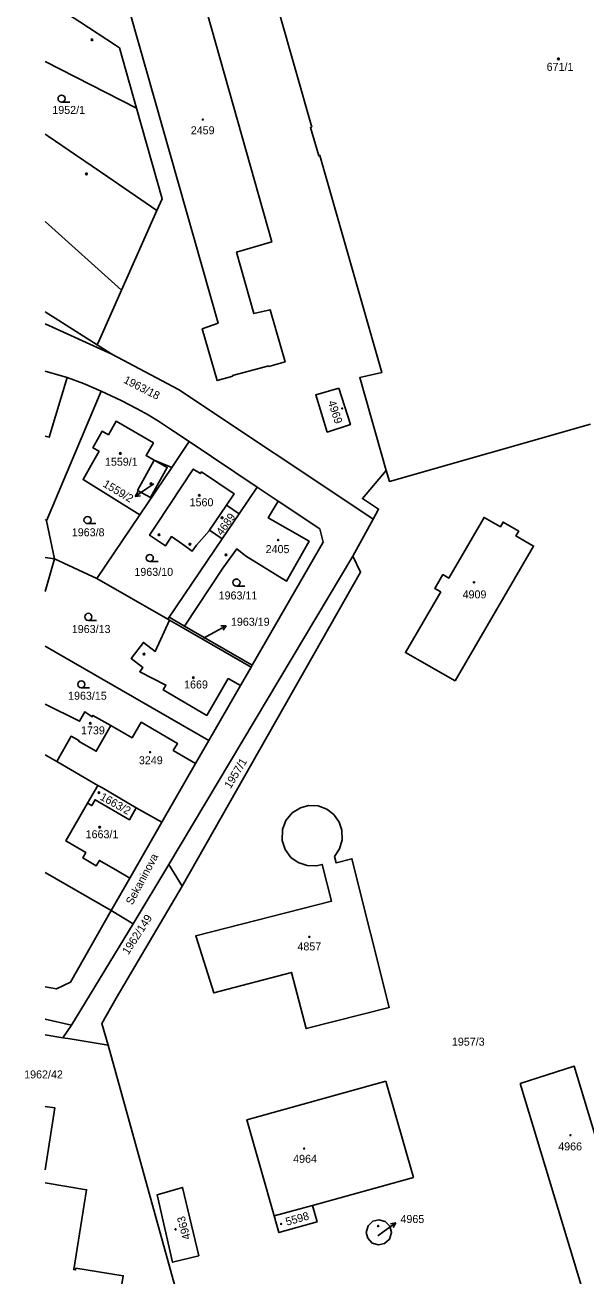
# Model space of a CAD drawing. Extents: x -667048 to -665920, y -1108425 to -1107247.
# Drawn here: x -667047.7 to -666928.5, y -1107866.2 to -1107600.6 of the extents above; entities that cross this region are included whole.
import ezdxf

# ---------------------------------------------------------------- set-up
doc = ezdxf.new("R2010")
doc.units = 0
for name, color, linetype in [('Default', 7, 'Continuous'), ('Hranice parcel', 7, 'Continuous'), ('Parcelní čísla', 7, 'Continuous'), ('Pop_ PČ_ popisy', 7, 'Continuous'), ('Značky budov', 7, 'Continuous'), ('Značky kultur', 7, 'Continuous')]:
    doc.layers.add(name, color=color, linetype=linetype)

# ---------------------------------------------------------------- blocks, each defined once
blk = doc.blocks.new('3.041')
at = {"layer": 'Default'}
blk.add_line((8, 0), (1758, 0), dxfattribs=at)
blk.add_circle((8, 750), 750, dxfattribs=at)
blk = doc.blocks.new('4.021')
at = {"layer": 'Default'}
blk.add_circle((-7, 1), 175, dxfattribs=at)
blk = doc.blocks.new('10291')
at = {"layer": 'Default'}
for p, q in [((0, 3001), (-500, 2001)), ((0, 1), (0, 3001)), ((0, 3001), (500, 2001))]:
    blk.add_line(p, q, dxfattribs=at)

msp = doc.modelspace()

# ---------------------------------------------------------------- linework, layer by layer
at = {"layer": 'Hranice parcel'}
for points in [[(-666970.95, -1107695.22), (-666976.59, -1107675.49), (-666971.89, -1107674.42), (-666985.05, -1107628.31), (-666985.31, -1107628.39), (-666987.06, -1107622.39), (-666986.8, -1107622.31), (-667000.62, -1107573.5), (-667000.76, -1107573.54), (-667001.78, -1107570.07), (-666998.23, -1107568.96), (-666998.83, -1107566.87), (-666996.16, -1107566.11), (-666996.94, -1107562.47), (-666921.16, -1107540.78), (-666917.42, -1107543.09), (-666913.29, -1107542), (-666908.38, -1107559.19), (-666898.23, -1107556.28), (-666897.4, -1107559.14)], [(-667021.52, -1107584.2), (-667013.51, -1107581.95), (-666995.3, -1107646.66), (-667002.77, -1107648.84), (-666999.12, -1107661.88), (-666995.66, -1107661.07), (-666992.44, -1107672.12), (-666995.9, -1107673.13), (-666995.94, -1107672.98)], [(-666995.94, -1107672.98), (-667003.61, -1107675.01), (-667003.57, -1107675.15), (-667006.92, -1107676.1), (-667010.04, -1107665.09), (-667006.69, -1107663.93), (-667028.7, -1107586.32)], [(-667043.07, -1107595.39), (-667036.05, -1107599.95), (-667028.46, -1107604.89), (-667027.63, -1107605.43)], [(-667027.63, -1107605.43), (-667024.02, -1107618.24)], [(-667024.02, -1107618.24), (-667043.46, -1107608.33)], [(-667024.02, -1107618.24), (-667018.59, -1107637.51), (-667019.68, -1107639.97)], [(-667043.46, -1107623.77), (-667042.77, -1107624.24), (-667036.78, -1107628.32), (-667030.12, -1107632.86)], [(-667030.12, -1107632.86), (-667019.68, -1107639.97)], [(-667027.19, -1107656.94), (-667043.46, -1107642.32)], [(-667019.68, -1107639.97), (-667027.19, -1107656.94)], [(-667027.19, -1107656.94), (-667031.86, -1107667.48), (-667032.38, -1107668.52)], [(-667043.46, -1107661.48), (-667032.38, -1107668.52)], [(-667029.24, -1107670.52), (-667043.46, -1107664.08)], [(-667032.38, -1107668.52), (-667029.24, -1107670.52)], [(-667029.24, -1107670.52), (-667015.09, -1107677.99), (-666974.26, -1107705.21)], [(-667043.46, -1107674.12), (-667038.79, -1107675.48)], [(-667043.46, -1107687.89), (-667042.57, -1107688.14), (-667038.79, -1107675.48)], [(-667038.79, -1107675.48), (-667035.28, -1107676.72), (-667031.56, -1107678.37)], [(-667043.12, -1107705.86), (-667031.56, -1107678.37)], [(-667031.56, -1107678.37), (-667027.28, -1107680.37), (-667023.88, -1107682.12), (-667021.55, -1107683.4), (-667019.34, -1107684.73), (-667016.79, -1107686.46), (-667012.8, -1107689.05)], [(-666981.07, -1107677.7), (-666978.58, -1107685.45), (-666983.5, -1107687.03), (-666985.93, -1107679.17), (-666981.07, -1107677.7)], [(-667016.53, -1107694.56), (-667020.24, -1107693.01), (-667021.99, -1107692.03), (-667020.44, -1107689.3), (-667028.37, -1107684.75), (-667030, -1107687.62), (-667031.32, -1107686.88), (-667031.94, -1107687.98), (-667033.3, -1107690.39), (-667031.99, -1107691.13), (-667033.67, -1107694.09), (-667035.39, -1107697.13), (-667023.34, -1107704.62)], [(-666927.58, -1107685.38), (-666970.29, -1107697.51), (-666970.95, -1107695.22)], [(-667016.53, -1107694.56), (-667012.8, -1107689.05)], [(-667012.8, -1107689.05), (-666998.38, -1107698.74)], [(-667020.24, -1107693.01), (-667017.5, -1107694.54), (-667021.06, -1107700.95), (-667023.81, -1107699.42), (-667020.24, -1107693.01)], [(-667023.34, -1107704.62), (-667016.53, -1107694.56)], [(-667004.92, -1107702.55), (-667003.3, -1107700.14), (-667010.21, -1107695.52), (-667010.44, -1107695.86), (-667011.95, -1107694.9), (-667016.94, -1107702.44), (-667019.97, -1107707.01), (-667021.25, -1107708.95), (-667017.86, -1107711.18), (-667016.6, -1107709.22), (-667014.22, -1107710.84), (-667012.17, -1107712.33), (-667011.26, -1107711.06), (-667008.6, -1107708.03), (-667008.49, -1107707.87)], [(-666973.75, -1107705.53), (-666972.58, -1107703.4), (-666976.03, -1107701.17), (-666970.95, -1107695.22)], [(-667002.2, -1107704.37), (-666998.38, -1107698.74)], [(-666998.38, -1107698.74), (-666993.92, -1107701.7)], [(-666993.92, -1107701.7), (-666996.03, -1107705.26), (-666987.35, -1107710.2), (-666992.13, -1107718.67), (-667000.87, -1107713.31), (-667002.68, -1107711.81), (-667005.65, -1107715.91), (-667013.81, -1107728.26)], [(-667008.49, -1107707.87), (-667004.92, -1107702.55)], [(-667002.2, -1107704.37), (-667004.92, -1107702.55)], [(-666985.05, -1107707.59), (-666993.92, -1107701.7)], [(-667043.12, -1107705.86), (-667043.46, -1107705.61)], [(-667041.46, -1107713.99), (-667043.12, -1107705.86)], [(-667032.48, -1107718.11), (-667023.34, -1107704.62)], [(-667005.79, -1107709.69), (-667002.2, -1107704.37)], [(-666973.75, -1107705.53), (-666978.06, -1107713.42)], [(-666974.26, -1107705.21), (-666973.75, -1107705.53)], [(-666959.36, -1107720.99), (-666960.62, -1107720.26), (-666958.91, -1107717.31), (-666957.66, -1107718.04), (-666950.19, -1107705.15), (-666946.72, -1107707.16), (-666946.14, -1107706.16), (-666942.82, -1107708.09), (-666943.4, -1107709.08), (-666939.65, -1107711.25), (-666956.32, -1107739.85)], [(-667008.49, -1107707.87), (-667005.79, -1107709.69)], [(-666999.44, -1107736.57), (-666984.38, -1107710.4), (-666985.05, -1107707.59)], [(-667017.09, -1107726.36), (-667005.79, -1107709.69)], [(-667041.46, -1107713.99), (-667043.46, -1107713.67)], [(-667043.46, -1107720.92), (-667041.46, -1107713.99)], [(-667041.46, -1107713.99), (-667032.48, -1107718.11)], [(-666978.06, -1107713.42), (-667017.13, -1107778.9)], [(-667014.34, -1107783.5), (-666976.43, -1107716.82), (-666978.06, -1107713.42)], [(-667032.48, -1107718.11), (-667017.35, -1107726.75)], [(-666956.32, -1107739.85), (-666966.89, -1107733.85), (-666959.36, -1107720.99)], [(-667016.98, -1107726.96), (-667020.05, -1107733.63), (-667022.56, -1107731.7), (-667025.18, -1107735.1), (-667022.65, -1107737.04), (-667023.35, -1107737.94), (-667017.77, -1107740.76), (-667018.37, -1107741.8), (-667009.09, -1107747.2), (-667004.53, -1107739.38), (-667001.92, -1107740.86)], [(-667017.35, -1107726.75), (-667017.09, -1107726.36)], [(-667016.98, -1107726.96), (-667017.35, -1107726.75)], [(-667013.81, -1107728.26), (-667017.09, -1107726.36)], [(-666999.67, -1107736.98), (-667014.06, -1107728.65), (-667016.98, -1107726.96)], [(-667013.81, -1107728.26), (-666999.44, -1107736.57)], [(-667008.67, -1107752.53), (-667043.46, -1107732.53)], [(-666999.67, -1107736.98), (-667001.92, -1107740.86)], [(-666999.44, -1107736.57), (-666999.67, -1107736.98)], [(-667001.92, -1107740.86), (-667008.67, -1107752.53)], [(-667043.46, -1107744.79), (-667036.12, -1107748.44), (-667034.97, -1107746.43), (-667033.43, -1107747.48), (-667033.27, -1107747.2), (-667029.48, -1107749.37)], [(-667040.97, -1107756.99), (-667037.93, -1107751.64), (-667036.26, -1107752.51), (-667036.34, -1107752.66), (-667032.59, -1107754.81), (-667029.48, -1107749.37)], [(-667029.48, -1107749.37), (-667024.97, -1107751.96), (-667023, -1107748.65), (-667015.34, -1107753.17), (-667016.22, -1107754.65), (-667014.51, -1107755.66), (-667011.49, -1107757.44)], [(-667011.49, -1107757.44), (-667008.67, -1107752.53)], [(-667043.46, -1107755.56), (-667040.97, -1107756.99)], [(-667032.26, -1107762.07), (-667040.97, -1107756.99)], [(-667011.49, -1107757.44), (-667018.64, -1107769.87)], [(-667032.26, -1107762.07), (-667034.41, -1107765.82)], [(-667024.07, -1107766.86), (-667031.39, -1107762.52), (-667032.26, -1107762.07)], [(-667034.41, -1107765.82), (-667039.03, -1107773.87), (-667034.76, -1107776.34), (-667035.42, -1107777.47), (-667032.56, -1107779.14), (-667031.9, -1107778), (-667028.04, -1107780.24), (-667025.46, -1107781.74)], [(-667024.07, -1107766.86), (-667025.52, -1107769.36), (-667032.81, -1107765.11), (-667033.48, -1107766.34), (-667034.41, -1107765.82)], [(-667018.64, -1107769.87), (-667024.07, -1107766.86)], [(-666990.92, -1107767.86), (-666989.2, -1107766.82), (-666987.46, -1107766.36), (-666985.41, -1107766.44), (-666983.57, -1107767.14), (-666982.08, -1107768.26), (-666980.98, -1107769.85), (-666980.37, -1107771.57), (-666980.35, -1107773.6), (-666980.9, -1107775.51), (-666981.96, -1107777.15), (-666981.63, -1107778.49), (-666978.24, -1107777.63), (-666970.31, -1107809.21), (-666987.95, -1107813.7), (-666991.09, -1107801.78), (-667007.6, -1107806.13), (-667011.45, -1107793.99), (-666982.58, -1107786.64), (-666984.56, -1107778.86), (-666985.75, -1107779.16), (-666987.76, -1107779.11), (-666989.71, -1107778.46), (-666991.21, -1107777.38), (-666992.46, -1107775.7), (-666993.08, -1107773.79), (-666992.99, -1107771.46), (-666992.27, -1107769.53), (-666990.92, -1107767.86)], [(-667018.64, -1107769.87), (-667025.46, -1107781.74)], [(-667024.75, -1107791.46), (-667017.13, -1107778.9)], [(-667017.13, -1107778.9), (-667014.34, -1107783.5)], [(-667043.46, -1107780.58), (-667029.42, -1107788.65)], [(-667025.46, -1107781.74), (-667029.42, -1107788.65)], [(-667014.34, -1107783.5), (-667028.38, -1107807.25), (-667031.41, -1107812.61), (-667030.05, -1107817.21)], [(-667043.46, -1107804.86), (-667041.01, -1107805.24), (-667038.08, -1107803.86), (-667029.42, -1107788.65)], [(-667029.42, -1107788.65), (-667024.75, -1107791.46)], [(-667037.81, -1107812.96), (-667024.75, -1107791.46)], [(-667037.81, -1107812.96), (-667043.46, -1107811.71)], [(-667039.67, -1107815.65), (-667037.81, -1107812.96)], [(-667043.46, -1107815.03), (-667039.67, -1107815.65)], [(-667030.05, -1107817.21), (-667038.12, -1107815.9), (-667039.67, -1107815.65)], [(-667030.05, -1107817.21), (-667003.54, -1107912.79)], [(-666942.5, -1107825.4), (-666931.02, -1107821.66), (-666917.67, -1107865.87), (-666929.14, -1107869.61), (-666942.5, -1107825.4)], [(-666994.78, -1107853.5), (-667000.6, -1107833.05), (-666971.07, -1107824.87)], [(-666971.07, -1107824.87), (-666965.16, -1107845.35)], [(-667043.46, -1107830.23), (-667041.35, -1107830.57), (-667043.46, -1107843.7)], [(-667043.46, -1107846.47), (-667034.62, -1107847.92), (-667037.37, -1107864.87), (-667036.96, -1107864.94), (-667036.89, -1107864.56), (-667026.84, -1107866.2), (-667031.79, -1107896.83), (-667041.86, -1107895.2), (-667041.79, -1107894.82), (-667043.46, -1107894.55)], [(-666965.16, -1107845.35), (-666986.66, -1107851.25)], [(-667010.75, -1107861.94), (-667016.37, -1107863.34), (-667019.63, -1107849.01), (-667014.24, -1107847.43), (-667010.75, -1107861.94)], [(-666986.66, -1107851.25), (-666985.66, -1107854.76), (-666993.78, -1107857.01), (-666994.78, -1107853.5)], [(-666994.78, -1107853.5), (-666986.66, -1107851.25)], [(-666975.2, -1107856.98), (-666974.81, -1107855.58), (-666973.81, -1107854.63), (-666972.52, -1107854.3), (-666971.16, -1107854.67), (-666970.19, -1107855.65), (-666969.84, -1107856.98), (-666970.28, -1107858.45), (-666971.3, -1107859.36), (-666972.64, -1107859.65), (-666973.95, -1107859.24), (-666974.88, -1107858.24), (-666975.2, -1107856.98)]]:
    msp.add_lwpolyline(points, dxfattribs=at)
at = {"layer": 'Pop_ PČ_ popisy'}
for points in [[(-667020.33, -1107698.03), (-667021.82, -1107699.04)], [(-667009.82, -1107730.82), (-667007.59, -1107729.61)], [(-666972.78, -1107857.74), (-666971.38, -1107856.74)]]:
    msp.add_lwpolyline(points, dxfattribs=at)

# ---------------------------------------------------------------- block references
for p, xscale, yscale, rotation in [((-667021.82, -1107699.04), 0.001, 0.001, 124.00000003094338), ((-667007.59, -1107729.61), 0.001, 0.0010000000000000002, -61.00000001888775), ((-666971.38, -1107856.74), 0.0010000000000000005, 0.0010000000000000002, -53.99999995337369)]:
    msp.add_blockref('10291', p, dxfattribs=dict(at, xscale=xscale, yscale=yscale, rotation=rotation))
at = {"layer": 'Značky budov'}
for p, xscale, yscale in [((-667033.46, -1107603.75), 0.0010000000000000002, 0.0010000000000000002), ((-666934.37, -1107607.8), 0.0010000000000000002, 0.0010000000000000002), ((-667009.92, -1107620.69), 0.0006700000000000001, 0.0006700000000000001), ((-667034.65, -1107632.22), 0.0010000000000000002, 0.0010000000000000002), ((-666980.3, -1107682.02), 0.0006700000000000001, 0.0006700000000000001), ((-667027.44, -1107691.59), 0.0010000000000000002, 0.0010000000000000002), ((-667020.91, -1107698.03), 0.0010000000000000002, 0.0010000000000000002), ((-667010.68, -1107700.47), 0.0010000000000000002, 0.0010000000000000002), ((-667005.82, -1107705.24), 0.0010000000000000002, 0.0010000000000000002), ((-667019.25, -1107708.86), 0.0010000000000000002, 0.0010000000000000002), ((-667012.68, -1107710.86), 0.0010000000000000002, 0.0010000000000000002), ((-666993.92, -1107709.95), 0.0006700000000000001, 0.0006700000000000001), ((-667004.99, -1107713.12), 0.0010000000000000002, 0.0010000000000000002), ((-666952.31, -1107718.96), 0.0006700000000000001, 0.0006700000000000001), ((-667022.44, -1107734.19), 0.0010000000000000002, 0.0010000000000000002), ((-667011.94, -1107739.2), 0.0010000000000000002, 0.0010000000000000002), ((-667033.84, -1107748.88), 0.0010000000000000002, 0.0010000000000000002), ((-667021.13, -1107755.02), 0.0006700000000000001, 0.0006700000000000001), ((-667031.98, -1107763.62), 0.0010000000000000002, 0.0010000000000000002), ((-667031.85, -1107770.94), 0.0010000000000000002, 0.0010000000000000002), ((-666987.29, -1107794.24), 0.0006700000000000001, 0.0006700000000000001), ((-666931.8, -1107836.36), 0.0006700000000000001, 0.0006700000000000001), ((-666988.39, -1107839.19), 0.0006700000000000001, 0.0006700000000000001), ((-667015.72, -1107856.33), 0.0006700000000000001, 0.0006700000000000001), ((-666993.29, -1107855.19), 0.0006700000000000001, 0.0006700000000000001), ((-666972.67, -1107855.62), 0.0006700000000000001, 0.0006700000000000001)]:
    msp.add_blockref('4.021', p, dxfattribs=dict(at, xscale=xscale, yscale=yscale))
at = {"layer": 'Značky kultur', "xscale": 0.0010000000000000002, "yscale": 0.0010000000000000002}
for p in [(-667039.95, -1107617), (-667034.44, -1107706.49), (-667021.21, -1107714.54), (-667002.79, -1107719.75), (-667034.26, -1107727.03), (-667035.75, -1107741.36)]:
    msp.add_blockref('3.041', p, dxfattribs=at)

# ---------------------------------------------------------------- texts
at = {"layer": 'Parcelní čísla'}
for s, p in [('671/1', (-666936.88, -1107610.34)), ('1952/1', (-667041.91, -1107619.49)), ('2459', (-667012.49, -1107623.81)), ('1559/1', (-667030.73, -1107694.19)), ('1560', (-667012.74, -1107702.8)), ('1963/8', (-667037.77, -1107709.17)), ('2405', (-666996.59, -1107712.75)), ('1963/10', (-667024.47, -1107717.58)), ('1963/11', (-667006.57, -1107722.59)), ('4909', (-666954.74, -1107722.36)), ('1963/19', (-667003.96, -1107728.17)), ('1963/13', (-667037.77, -1107729.72)), ('1669', (-667013.91, -1107741.49)), ('1963/15', (-667038.56, -1107743.88)), ('1739', (-667035.81, -1107751.23)), ('3249', (-667023.51, -1107757.58)), ('1663/1', (-667034.83, -1107773.29)), ('4857', (-666989.83, -1107797.11)), ('1957/3', (-666957.01, -1107817.34)), ('1962/42', (-667047.89, -1107824.29)), ('4966', (-666934.42, -1107839.58)), ('4964', (-666990.74, -1107842.21)), ('4965', (-666967.94, -1107854.99))]:
    msp.add_text(s, height=1.7, dxfattribs=at).set_placement(p)
for s, rotation, p in [('1963/18', 333, (-667026.93, -1107676.5)), ('4969', 288, (-666983.38, -1107680.64)), ('1559/2', 329, (-667031.31, -1107698.51)), ('4689', 54, (-667005.87, -1107709.14)), ('1957/1', 59, (-667004.04, -1107762.9)), ('1663/2', 331, (-667031.93, -1107765)), ('1962/149', 57, (-667025.76, -1107798.15)), ('4963', 105, (-667012.51, -1107858.29)), ('5598', 16, (-666992.07, -1107855.59))]:
    msp.add_text(s, height=1.7, rotation=rotation, dxfattribs=at).set_placement(p)
at = {"layer": 'Pop_ PČ_ popisy'}
msp.add_text('Sekaninova', height=1.7, rotation=62, dxfattribs=at).set_placement((-667024.91, -1107787.6))

doc.saveas('drawing.dxf')
